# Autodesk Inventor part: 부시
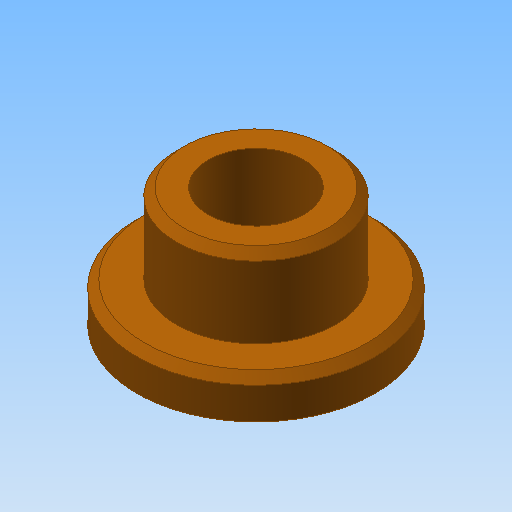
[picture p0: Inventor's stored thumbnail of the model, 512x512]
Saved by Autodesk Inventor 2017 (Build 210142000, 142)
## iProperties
Created: 2016-02
Part Number: 부시
Material: 스테인리스강
Document SubType Name: Modeling
Designer: mduedu
Density: 8.08 g/cm^3
Appearance: 주황색
Mass: 39.4553 g
Surface Area: 27.3717 cm^2
Volume: 4.88308 cm^3
Author: mduedu
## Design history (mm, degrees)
sketch "스케치1"
  geometry: C1 r 15 at (0, 0); 1 further point
  constraints: 1 centre point, 1 coincident
  dimensions: "d0" = 30 diameter of C1
extrude "돌출1" new body sketch "스케치1" distance "d1" = 5; taper "d2" = 0 deg
sketch "스케치2"
  geometry: C1 r 10 at (0, 0); 1 further point
  constraints: 1 centre point, 1 coincident
  dimensions: "d3" = 20 diameter of C1
extrude "돌출2" join sketch "스케치2" distance "d4" = 10; taper "d5" = 0 deg
hole "구멍1" diameter "d8" = 12; stored, may be unused: countersink angle "d12" = 90 deg, drill point angle "d14" = 118 deg; dims "d9" = 6, "d10" = 4, "d11" = 2, "d13" = 8, "d15" = 10, "d16" = 10
chamfer "모따기1" distance "d17" = 1; stored, may be unused: second distance "d18" = 2, angle "d19" = 45 deg
chamfer "모따기2" distance "d20" = 1; stored, may be unused: second distance "d21" = 2, angle "d22" = 45 deg
chamfer "모따기3" distance "d23" = 1; stored, may be unused: second distance "d24" = 2, angle "d25" = 45 deg
node "솔리드1"
